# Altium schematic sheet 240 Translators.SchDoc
size Letter; Organization: Toradex Solutions Inc.; Address1: 6415 Northwest Drive; Address2: Mississauga, ON, L4V 1X1; Address3: Canada
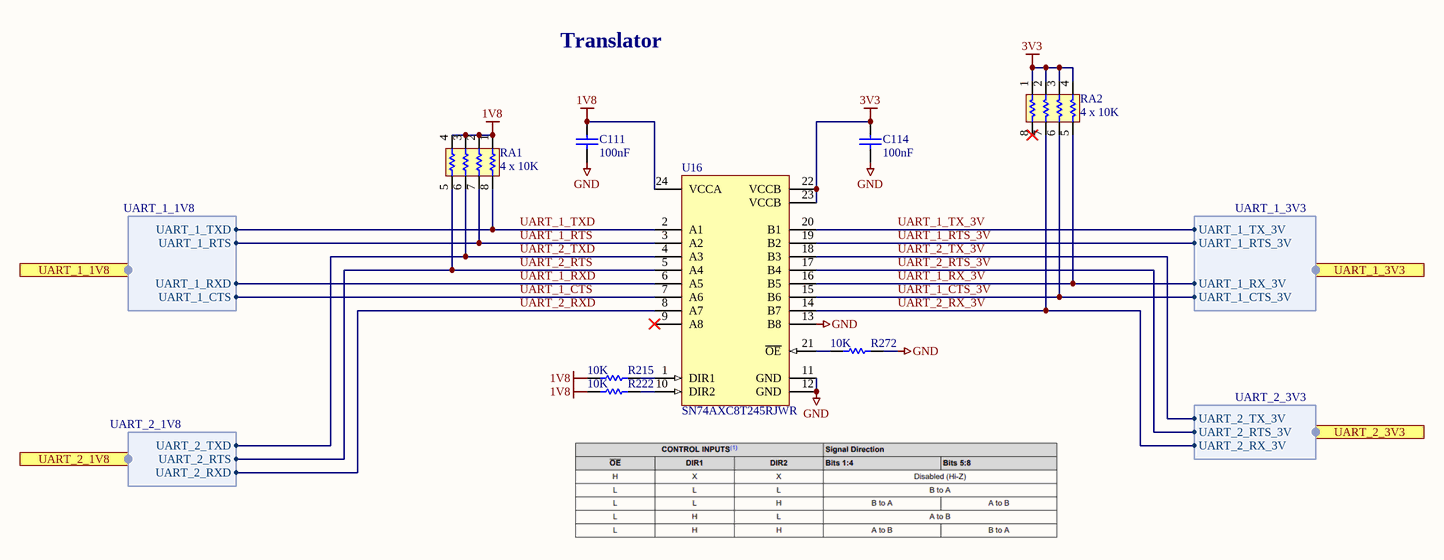
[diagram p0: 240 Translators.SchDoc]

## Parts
C111  100nF  [C0402_CAPC1005L]
C114  100nF  [C0402_CAPC1005L]
R215  value 10K  [R0402_RESC1005L]  (hidden comment: 1572-Res-0402-10K)
R222  value 10K  [R0402_RESC1005L]  (hidden comment: 1572-Res-0402-10K)
R272  value 10K  [R0402_RESC1005L]  (hidden comment: 1572-Res-0402-10K)
RA1  value 4 x 10K  [RESNET-1206-4]  (hidden comment: 1407-ResArr-1206-10K)
RA2  value 4 x 10K  [RESNET-1206-4]  (hidden comment: 1407-ResArr-1206-10K)
U16  SN74AXC8T245RJWR  [UQFN-24]

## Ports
UART_1_1V8 (harness UART_1_1V8), UART_1_3V3 (harness UART_1_3V3), UART_2_1V8 (harness UART_2_1V8), UART_2_3V3 (harness UART_2_3V3)

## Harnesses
UART_1_1V8: UART_1_RXD, UART_1_TXD, UART_1_RTS, UART_1_CTS
UART_2_1V8: UART_2_RXD, UART_2_TXD, UART_2_RTS
UART_2_3V3: UART_2_RX_3V, UART_2_TX_3V, UART_2_RTS_3V
UART_1_3V3: UART_1_RX_3V, UART_1_TX_3V, UART_1_RTS_3V, UART_1_CTS_3V

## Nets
1V8: C111.2 R215.1 R222.1 RA1.1 RA1.2 RA1.3 RA1.4 U16.24(VCCA)
3V3: C114.2 RA2.1 RA2.2 RA2.3 RA2.4 U16.22(VCCB) U16.23(VCCB)
GND: C111.1 C114.1 R272.2 U16.11(GND) U16.12(GND) U16.13(B8)
UART_1_CTS: U16.7(A6) ; port UART_1_1V8.UART_1_CTS
UART_1_CTS_3V: RA2.6 U16.15(B6) ; port UART_1_3V3.UART_1_CTS_3V
UART_1_RTS: RA1.7 U16.3(A2) ; port UART_1_1V8.UART_1_RTS
UART_1_RTS_3V: U16.19(B2) ; port UART_1_3V3.UART_1_RTS_3V
UART_1_RX_3V: RA2.5 U16.16(B5) ; port UART_1_3V3.UART_1_RX_3V
UART_1_RXD: U16.6(A5) ; port UART_1_1V8.UART_1_RXD
UART_1_TX_3V: U16.20(B1) ; port UART_1_3V3.UART_1_TX_3V
UART_1_TXD: RA1.8 U16.2(A1) ; port UART_1_1V8.UART_1_TXD
UART_2_RTS: RA1.5 U16.5(A4) ; port UART_2_1V8.UART_2_RTS
UART_2_RTS_3V: U16.17(B4) ; port UART_2_3V3.UART_2_RTS_3V
UART_2_RX_3V: RA2.7 U16.14(B7) ; port UART_2_3V3.UART_2_RX_3V
UART_2_RXD: U16.8(A7) ; port UART_2_1V8.UART_2_RXD
UART_2_TX_3V: U16.18(B3) ; port UART_2_3V3.UART_2_TX_3V
UART_2_TXD: RA1.6 U16.4(A3) ; port UART_2_1V8.UART_2_TXD
NetR215_2: R215.2 U16.1(DIR1)
NetR222_2: R222.2 U16.10(DIR2)
NetR272_1: R272.1 U16.21(~{OE})

Not connected (* = marked no-connect by the designer): RA2 8*; U16 9(A8)*

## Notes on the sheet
- Translator

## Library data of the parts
C111 C114 = 1566-Cap-0402-100nF/50V: (-55 to 125 DegC AEC) Cap Ceramic 0.1uF 50V X7R 10% 0402; MfrNo: GRT155R71H104KE01D; Mfr: Murata; Alt: CL05B104KB54PNC,GCM155R71H104ME02D,GCM155R71H104KE02D,GCM155R71H104KE02J; PN: 1566
R215 R222 R272 = 1572-Res-0402-10K: (-55 to 155 DegC AEC) RES 10K OHM 1% 1/16W 100ppm 0402; Mfr: Stackpole Electronics; MfrNo: RMCF0402FT10K0; Alt: AC0402FR-0710KL,AC0402FR-1310KL,CRGCQ0402F10K; PN: 1572
RA1 RA2 = 1407-ResArr-1206-10K: (-55 to 125 DegC) RES ARRAY 4 RES 10K 1% 200ppm 1206; Mfr: Yageo; MfrNo: TC164-FR-0710KL; PN: 1407; Alt: YC164-FR-0710KL
U16 = 2540-SN74AXC8T245RJWR: (-40 to 125 DegC) IC TRANSLATION TXRX 0.65-3.6V 24UQFN; Mfr: Texas Instruments; PN: 2540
